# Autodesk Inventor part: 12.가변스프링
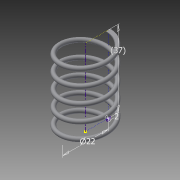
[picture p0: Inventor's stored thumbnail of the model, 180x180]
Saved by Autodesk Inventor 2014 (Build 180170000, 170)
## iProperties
Created: 2016-01
Part Number: 12.가변스프링
Material: Generic
Document SubType Name: Modeling
Designer: Administrator
Density: 1 g/cm^3
Appearance: Default
Author: Administrator
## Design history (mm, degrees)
sketch "스케치1"
  geometry: L1 (0, 37)-(11, 37); L2 (11, 37)-(11, 0); L3 (11, 0)-(0, 0); L4 (0, 0)-(0, 37); C1 r 1 at (11, 0); 1 further point
  constraints: 8 end point, 2 coincident, 2 parallel, 1 centre point, 1 horizontal, 1 perpendicular
  dimensions: "d0" = 2 diameter of C1; "d1" = 22 diameter of L2 L4; "d2" = 37 distance of L1.end L2.end (derived)
feature "코일1" pitch "d3" = 10; turns "d5" = 5; dims "d4" = 37 (= d2), "d6" = 0, angle "d7" = 90 deg, angle "d8" = 90 deg, "d9" = 0, "d10" = 0
sketch "스케치2"
  geometry: L1 (0, 12)-(0, 10) reference; 1 further point
  constraints: 1 vertical alignment
extrude "돌출1" cut sketch "스케치2" distance "d11" = 10; taper "d12" = 0 deg
node "작업 평면1"
sketch "스케치3"
  geometry: L1 (10, 0)-(12, 0) reference; 1 further point
  constraints: 1 horizontal alignment
extrude "돌출2" cut sketch "스케치3" distance "d14" = 10; taper "d15" = 0 deg
node "솔리드1"
node "절단 모서리 투영1"
node "절단 모서리 투영2"
other parameters: "d13" = 0
